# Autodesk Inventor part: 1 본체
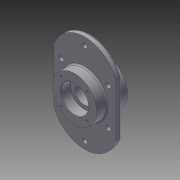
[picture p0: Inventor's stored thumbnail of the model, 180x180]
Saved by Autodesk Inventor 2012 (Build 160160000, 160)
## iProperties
Created: 2015-02
Part Number: 1 본체
Material: 알루미늄-6061
Document SubType Name: Modeling
Designer: Class3-User
Density: 2.71 g/cm^3
Mass: 1635.99 g
Surface Area: 894.151 cm^2
Volume: 603.686 cm^3
Author: Class3-User
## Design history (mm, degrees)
sketch "스케치1"
  geometry: L1 (-70, -60)-(-70, 60); L2 (70, 60)-(70, -60); L3 (70, 0)-(-70, 0); L4 (0, -36)-(0, 36); A1 r 74 centre (0, -36) between (-70, -60) and (70, -60); A2 r 74 centre (0, 36) between (70, 60) and (-70, 60); 4 further points
  constraints: 8 end point, 6 point on circle, 3 midpoint, 2 centre point, 2 parallel, 2 vertical, 1 coincident, 2 other
  dimensions: "d0" = 120 distance of L1.start L1.end; "d2" = 140 distance between parallel lines of L1 L2; "d3" = 220 distance of point (0, -110) point (0, 110)
extrude "돌출1" new body sketch "스케치1" distance "d4" = 12; taper "d5" = 0 deg
node "작업 평면1"
sketch "스케치2"
  geometry: C1 r 50 at (0, 0); 1 further point
  constraints: 1 centre point, 1 coincident
  dimensions: "d7" = 100 diameter of C1
extrude "돌출2" join sketch "스케치2" distance "d8" = 70; taper "d9" = 0 deg
sketch "스케치3"
  geometry: C1 r 50 at (0, 0) reference; C2 r 31 at (0, 0)
  constraints: 1 centre point, 1 coincident
  dimensions: "d10" = 62 diameter of C2
extrude "돌출3" cut sketch "스케치3" distance "d11" = 22; taper "d12" = 0 deg
sketch "스케치4"
  geometry: C1 r 50 at (0, 0) reference; C2 r 31 at (0, 0)
  constraints: 1 centre point, 1 coincident
  dimensions: "d13" = 62 diameter of C2
extrude "돌출4" cut sketch "스케치4" distance "d14" = 22; taper "d15" = 0 deg
sketch "스케치5"
  geometry: C1 r 31 at (0, 0) reference; C2 r 22.5 at (0, 0)
  constraints: 1 centre point, 1 coincident
  dimensions: "d16" = 45 diameter of C2
extrude "돌출5" cut sketch "스케치5" stored distance "d17" = 22; taper "d18" = 0 deg
sketch "스케치6"
  geometry: L1 (0, 41)-(0, 0); L2 (0, 0)-(28.991, 28.991); C1 r 50 at (0, 0) reference; A1 r 41 centre (0, 0) between (0, 41) and (28.991, 28.991); 1 further point
  constraints: 4 end point, 2 coincident, 2 point on circle, 1 centre point, 1 vertical
  dimensions: "d19" = 82 diameter of A1; "d20" = 45 deg angle of L1 L2
hole "구멍1" sketch "스케치6" at (28.991, 28.991) diameter "d21" = 4.917; stored, may be unused: countersink angle "d25" = 90 deg, drill point angle "d27" = 118 deg; dims "d22" = 10, "d23" = 4, "d24" = 2, "d26" = 13
sketch "스케치7"
  geometry: L1 (0, 41)-(0, 0); L2 (0, 0)-(28.991, 28.991); C1 r 50 at (0, 0) reference; A1 r 41 centre (0, 0) between (0, 41) and (28.991, 28.991); 1 further point
  constraints: 4 end point, 2 coincident, 2 point on circle, 1 centre point, 1 vertical
  dimensions: "d31" = 82 diameter of A1; "d32" = 45 deg angle of L2 L1
hole "구멍2" sketch "스케치7" at (28.991, 28.991) diameter "d33" = 4.917; stored, may be unused: countersink angle "d37" = 90 deg, drill point angle "d39" = 118 deg; dims "d34" = 10, "d35" = 4, "d36" = 2, "d38" = 13
fillet "모깎기1" dims "d43" = 0.3, "d47" = 3
chamfer "모따기1" distance "d44" = 1; stored, may be unused: second distance "d45" = 2, angle "d46" = 45 deg
sketch "스케치8"
  geometry: L1 (-70, 60)-(-70, -60) reference; L2 (70, -60)-(70, 60) reference; L3 (-53, 56.976)-(-53, -56.976); L4 (53, -56.976)-(53, 56.976); C1 r 10 at (0, 93); A1 r 74 centre (0, 36) between (70, 60) and (-70, 60) reference; A2 r 74 centre (0, -36) between (-70, -60) and (70, -60) reference; A3 r 57 centre (0, 36) between (53, 56.976) and (-53, 56.976); A4 r 57 centre (0, -36) between (-53, -56.976) and (53, -56.976); 2 further points
  constraints: 5 point on circle, 4 end point, 3 centre point, 2 coincident, 3 other
  dimensions: "d50" = 17 distance between parallel lines of L4 L2; "d51" = 20 diameter of C1
extrude "돌출6" join sketch "스케치8" distance "d52" = 5; taper "d53" = 0 deg
fillet "모깎기4" dims "d58" = 3
fillet "모깎기5" dims "d59" = 3
sketch "스케치11"
  geometry: L1 (-33.183, 69.803)-(33.183, 69.803); L2 (33.183, 69.803)-(33.183, 60.197); L3 (33.183, 60.197)-(-33.183, 60.197); L4 (-33.183, 60.197)-(-33.183, 69.803); L5 (-33.183, 65)-(33.183, 65); L6 (0, 65)-(0, 0); C1 r 53 at (0, 0) reference
  constraints: 4 end point, 3 midpoint, 1 vertical, 2 other
  dimensions: "d60" = 65 distance of L6.start L6.end
feature "엠보싱1" sketch "스케치11" dims "d61" = 1, "d62" = 0
sketch "스케치14"
  geometry: C1 r 10 at (0, 0) reference; C2 r 5.5 at (0, 0); 1 further point
  constraints: 1 centre point, 1 coincident
  dimensions: "d66" = 11 diameter of C2
extrude "돌출8" cut sketch "스케치14" stored distance "d67" = 0; taper "d68" = 0 deg
fillet "모깎기7" dims "d71" = 3
node "솔리드1"
pattern_circular "원형 패턴1" dims angle "d29" = 360 deg
pattern_circular "원형 패턴2" dims angle "d41" = 360 deg
pattern_linear "직사각형 패턴1"
sketch "스케치13"
  geometry: L1 (-70, -60)-(-70, 60) reference; L2 (70, 60)-(70, -60) reference; L3 (-53, 56.976)-(-53, -56.976); L4 (53, -56.976)-(53, 56.976); C1 r 5.5 at (0, -93) reference; A1 r 74 centre (0, -36) between (-70, -60) and (70, -60) reference; A2 r 74 centre (0, 36) between (70, 60) and (-70, 60) reference; A3 r 57 centre (0, -36) between (-53, -56.976) and (53, -56.976); A4 r 57 centre (0, 36) between (53, 56.976) and (-53, 56.976)
  constraints: 4 end point, 4 point on circle, 2 centre point, 3 other
  dimensions: "d65" = 17 radial gap between concentric circles of A4 A2
other parameters: "d6" = 23
